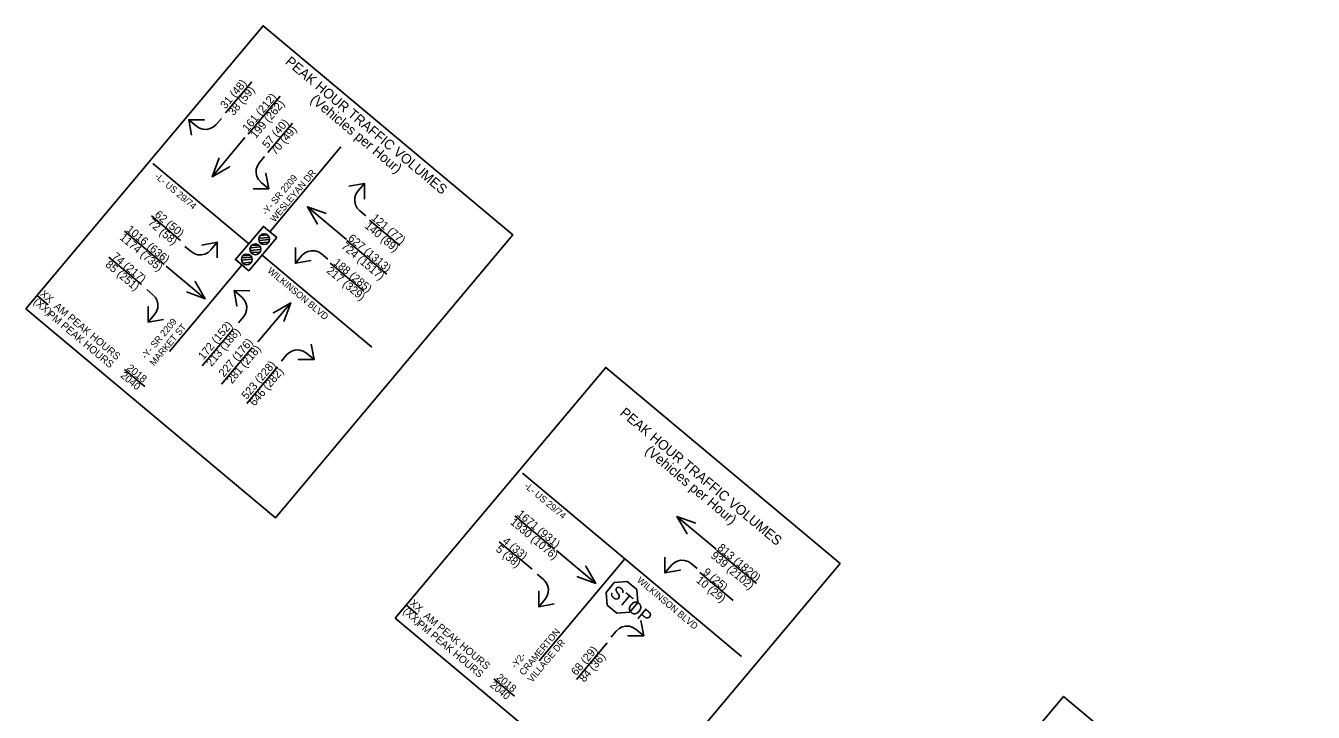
# Model space of a CAD drawing. Extents: x 1257249 to 1258387, y 800228 to 800957.
# Drawn here: x 1257736 to 1258387, y 800608 to 800956 of the extents above; entities that cross this region are included whole.
import ezdxf

# ---------------------------------------------------------------- set-up
doc = ezdxf.new("R2010")
doc.units = 0
for name, color, linetype in [('Exist PHM Traffic Signal CELL', 7, 'Continuous'), ('Pattern 1', 7, 'Continuous'), ('Prop DSN Text', 7, 'Continuous')]:
    doc.layers.add(name, color=color, linetype=linetype)

msp = doc.modelspace()

# ---------------------------------------------------------------- linework, layer by layer
at = {"layer": 'Exist PHM Traffic Signal CELL'}
for p, q in [((1257853.86, 800848.37), (1257859.23, 800848.84)), ((1257853.86, 800847.31), (1257859.33, 800847.7)), ((1257854.58, 800849.72), (1257858.32, 800850.1)), ((1257849.45, 800843.55), (1257854.6, 800843.96)), ((1257849.47, 800842.22), (1257854.84, 800842.69)), ((1257850.01, 800841.11), (1257854.56, 800841.38)), ((1257850.31, 800844.78), (1257853.71, 800844.94)), ((1257854.55, 800846.08), (1257858.77, 800846.45)), ((1257845.09, 800838.39), (1257850.34, 800838.72)), ((1257845.19, 800837.25), (1257850.56, 800837.72)), ((1257845.78, 800839.52), (1257849.57, 800839.85)), ((1257845.8, 800835.84), (1257849.98, 800836.25))]:
    msp.add_line(p, q, dxfattribs=at)
msp.add_lwpolyline([(1257862.94, 800848.75), (1257856.19, 800854.41), (1257842.05, 800837.55), (1257848.81, 800831.89)], close=True, dxfattribs=at)
for centre in [(1257856.58, 800847.91), (1257852.15, 800842.77), (1257847.79, 800837.65)]:
    msp.add_circle(centre, 2.74, dxfattribs=at)
at = {"layer": 'Pattern 1'}
for points in [[(1257834.94, 800909.07), (1257832.34, 800905.97), (1257830.97, 800904.72), (1257829.33, 800903.86), (1257827.53, 800903.46), (1257825.68, 800903.54), (1257823.91, 800904.1), (1257822.35, 800905.09), (1257818.47, 800908.34), (1257826.34, 800908.32), (1257818.47, 800908.34), (1257819.88, 800900.54)], [(1257846.88, 800899.31), (1257830.29, 800879.52), (1257839.06, 800884.59), (1257830.29, 800879.52), (1257833.75, 800889.04)], [(1257856.75, 800889.77), (1257854.15, 800886.66), (1257853.16, 800885.1), (1257852.6, 800883.34), (1257852.52, 800881.49), (1257852.93, 800879.68), (1257853.78, 800878.04), (1257855.03, 800876.68), (1257858.91, 800873.43), (1257857.52, 800881.17), (1257858.91, 800873.43), (1257850.98, 800873.45)], [(1257908.04, 800859.67), (1257904.93, 800862.27), (1257903.68, 800863.63), (1257902.83, 800865.27), (1257902.43, 800867.08), (1257902.51, 800868.93), (1257903.06, 800870.69), (1257904.05, 800872.25), (1257907.31, 800876.13), (1257907.29, 800868.26), (1257907.31, 800876.13), (1257899.5, 800874.72)], [(1257898.27, 800847.72), (1257878.48, 800864.31), (1257883.55, 800855.54), (1257878.48, 800864.31), (1257888, 800860.85)], [(1257816.49, 800844.2), (1257819.6, 800841.6), (1257821.16, 800840.6), (1257822.92, 800840.05), (1257824.77, 800839.97), (1257826.58, 800840.37), (1257828.22, 800841.23), (1257829.58, 800842.48), (1257832.83, 800846.36), (1257825.08, 800844.96), (1257832.83, 800846.36), (1257832.81, 800838.43)], [(1257816.49, 800844.2), (1257819.6, 800841.6), (1257821.16, 800840.6), (1257822.92, 800840.05), (1257824.77, 800839.97), (1257826.58, 800840.37), (1257828.22, 800841.23), (1257829.58, 800842.48), (1257832.83, 800846.36), (1257825.08, 800844.96), (1257832.83, 800846.36), (1257832.81, 800838.43)], [(1257888.73, 800837.85), (1257885.63, 800840.45), (1257884.07, 800841.44), (1257882.3, 800842), (1257880.45, 800842.08), (1257878.65, 800841.68), (1257877, 800840.82), (1257875.64, 800839.57), (1257872.39, 800835.69), (1257880.14, 800837.09), (1257872.39, 800835.69), (1257872.41, 800843.62)], [(1257806.95, 800834.32), (1257826.74, 800817.74), (1257821.67, 800826.5), (1257826.74, 800817.74), (1257817.22, 800821.2)], [(1257806.95, 800834.32), (1257826.74, 800817.74), (1257821.67, 800826.5), (1257826.74, 800817.74), (1257817.22, 800821.2)], [(1257797.18, 800822.38), (1257800.29, 800819.78), (1257801.54, 800818.42), (1257802.39, 800816.78), (1257802.8, 800814.97), (1257802.72, 800813.12), (1257802.16, 800811.36), (1257801.17, 800809.8), (1257797.92, 800805.92), (1257797.94, 800813.79), (1257797.92, 800805.92), (1257805.72, 800807.32)], [(1257797.18, 800822.38), (1257800.29, 800819.78), (1257801.54, 800818.42), (1257802.39, 800816.78), (1257802.8, 800814.97), (1257802.72, 800813.12), (1257802.16, 800811.36), (1257801.17, 800809.8), (1257797.92, 800805.92), (1257797.94, 800813.79), (1257797.92, 800805.92), (1257805.72, 800807.32)], [(1257843.55, 800805.51), (1257846.15, 800808.62), (1257847.15, 800810.18), (1257847.7, 800811.94), (1257847.78, 800813.79), (1257847.38, 800815.6), (1257846.52, 800817.24), (1257845.27, 800818.6), (1257841.39, 800821.85), (1257842.79, 800814.11), (1257841.39, 800821.85), (1257849.32, 800821.83)], [(1257853.43, 800795.97), (1257870.01, 800815.76), (1257861.25, 800810.69), (1257870.01, 800815.76), (1257866.55, 800806.24)], [(1257865.37, 800786.2), (1257867.97, 800789.31), (1257869.33, 800790.56), (1257870.97, 800791.41), (1257872.78, 800791.82), (1257874.63, 800791.74), (1257876.39, 800791.18), (1257877.95, 800790.19), (1257881.83, 800786.94), (1257873.96, 800786.96), (1257881.83, 800786.94), (1257880.42, 800794.74)], [(1258085.28, 800691), (1258065.49, 800707.58), (1258070.56, 800698.82), (1258065.49, 800707.58), (1258075.01, 800704.12)], [(1258004.56, 800690.25), (1258024.35, 800673.66), (1258019.28, 800682.43), (1258024.35, 800673.66), (1258014.83, 800677.12)], [(1258004.56, 800690.25), (1258024.35, 800673.66), (1258019.28, 800682.43), (1258024.35, 800673.66), (1258014.83, 800677.12)], [(1258075.74, 800681.12), (1258072.63, 800683.72), (1258071.07, 800684.72), (1258069.31, 800685.27), (1258067.46, 800685.35), (1258065.65, 800684.95), (1258064.01, 800684.09), (1258062.65, 800682.84), (1258059.4, 800678.96), (1258067.14, 800680.36), (1258059.4, 800678.96), (1258059.42, 800686.89)], [(1257994.79, 800678.3), (1257997.9, 800675.7), (1257999.15, 800674.34), (1258000, 800672.7), (1258000.41, 800670.89), (1258000.33, 800669.04), (1257999.77, 800667.28), (1257998.78, 800665.72), (1257995.53, 800661.84), (1257995.55, 800669.71), (1257995.53, 800661.84), (1258003.33, 800663.25)], [(1257994.79, 800678.3), (1257997.9, 800675.7), (1257999.15, 800674.34), (1258000, 800672.7), (1258000.41, 800670.89), (1258000.33, 800669.04), (1257999.77, 800667.28), (1257998.78, 800665.72), (1257995.53, 800661.84), (1257995.55, 800669.71), (1257995.53, 800661.84), (1258003.33, 800663.25)], [(1258032.18, 800646.4), (1258034.78, 800649.51), (1258036.15, 800650.76), (1258037.79, 800651.61), (1258039.59, 800652.01), (1258041.44, 800651.93), (1258043.21, 800651.38), (1258044.77, 800650.39), (1258048.65, 800647.13), (1258040.78, 800647.15), (1258048.65, 800647.13), (1258047.24, 800654.94)]]:
    msp.add_lwpolyline(points, dxfattribs=at)
at = {"layer": 'Prop DSN Text'}
for p, q in [((1257850.31, 800927.64), (1257837.1, 800911.88)), ((1257864.76, 800920.39), (1257848.53, 800901.02)), ((1257870.86, 800906.57), (1257858.49, 800891.81)), ((1257895.37, 800894.58), (1257859.44, 800851.71)), ((1257800.28, 800886.21), (1257848.63, 800845.69)), ((1257799.56, 800859.7), (1257814.33, 800847.32)), ((1257909.83, 800857.58), (1257925.26, 800844.64)), ((1257785.87, 800851.94), (1257805.97, 800835.09)), ((1257898.46, 800847.18), (1257918.68, 800830.24)), ((1257777.93, 800838.84), (1257794.53, 800824.92)), ((1257845.14, 800834.65), (1257808.66, 800791.11)), ((1257855.64, 800839.81), (1257911.11, 800793.32)), ((1257890.04, 800835.83), (1257906.96, 800821.65)), ((1257741.82, 800819.24), (1257747.25, 800814.69)), ((1257840.8, 800802.24), (1257825.29, 800783.74)), ((1257850.57, 800793.02), (1257835.06, 800774.51)), ((1257863.38, 800783.29), (1257847.87, 800764.78)), ((1257785.86, 800782), (1257796.29, 800773.26)), ((1257987.29, 800729.48), (1258039.02, 800686.12)), ((1257983.48, 800707.86), (1258003.58, 800691.02)), ((1257975.54, 800694.76), (1257992.14, 800680.84)), ((1258039.02, 800686.12), (1257995.67, 800634.39)), ((1258039.02, 800686.12), (1258098.12, 800636.59)), ((1258085.47, 800690.46), (1258105.68, 800673.52)), ((1258077.05, 800679.1), (1258093.97, 800664.92)), ((1258029.63, 800669.12), (1258033.76, 800674.05)), ((1258033.76, 800674.05), (1258040.21, 800674.63)), ((1258040.21, 800674.63), (1258045.16, 800670.49)), ((1258030.16, 800662.67), (1258029.63, 800669.12)), ((1258045.16, 800670.49), (1258045.71, 800664.03)), ((1257928.83, 800662.51), (1257934.26, 800657.96)), ((1258035.12, 800658.52), (1258030.16, 800662.67)), ((1258041.57, 800659.09), (1258035.12, 800658.52)), ((1258045.71, 800664.03), (1258041.57, 800659.09)), ((1258030.19, 800643.49), (1258014.68, 800624.98)), ((1257972.87, 800625.27), (1257983.29, 800616.53))]:
    msp.add_line(p, q, dxfattribs=at)
for points in [[(1257735.95, 800812.7), (1257862.29, 800706.82), (1257982.36, 800850.08), (1257856.02, 800955.96)], [(1257922.96, 800655.97), (1258041.53, 800556.6), (1258148, 800683.65), (1258029.43, 800783.02)], [(1258141.05, 800473.19), (1258267.38, 800367.31), (1258387.45, 800510.58), (1258261.11, 800616.46)]]:
    msp.add_lwpolyline(points, close=True, dxfattribs=at)

# ---------------------------------------------------------------- texts
for s, height, rotation, p in [('PEAK HOUR TRAFFIC VOLUMES', 5, 320.03429, (1257866.87, 800937.06)), ('31 (48)', 4.05, 50.03429, (1257837.04, 800913.57)), ('38 (59)', 4.05, 50.03429, (1257841.11, 800910.16)), ('161 (212)', 4.05, 50.03429, (1257848.27, 800901.97)), ('(Vehicles per Hour)', 5, 320.03429, (1257879.55, 800917.88)), ('199 (262)', 4.05, 50.03429, (1257852.34, 800898.56)), ('57 (40)', 4.05, 50.03429, (1257858.28, 800893.59)), ('70 (49)', 4.05, 50.03429, (1257862.35, 800890.18)), ('-L- US 29/74 ', 3.375, 320.03429, (1257800.97, 800879.17)), ('-Y- SR 2209', 3.375, 50.03429, (1257857.69, 800859.79)), ('WESLEYAN DR', 3.375, 50.03429, (1257861.89, 800856.27)), ('62 (50)', 4.05, 320.03429, (1257800.85, 800859.75)), ('1016 (636)', 4.05, 320.03429, (1257786.57, 800852.24)), ('72 (58)', 4.05, 320.03429, (1257797.44, 800855.68)), ('140 (89)', 4.05, 320.03429, (1257907.14, 800854.03)), ('121 (77)', 4.05, 320.03429, (1257910.55, 800858.1)), ('1174 (735)', 4.05, 320.03429, (1257783.16, 800848.17)), ('627 (1313)', 4.05, 320.03429, (1257898.68, 800847.81)), ('74 (217)', 4.05, 320.03429, (1257779.29, 800838.53)), ('724 (1517)', 4.05, 320.03429, (1257895.27, 800843.74)), ('85 (251)', 4.05, 320.03429, (1257775.88, 800834.46)), ('188 (285)', 4.05, 320.03429, (1257891.27, 800835.47)), ('WILKINSON BLVD', 3.375, 320.03429, (1257857.94, 800831.42)), ('217 (329)', 4.05, 320.03429, (1257887.86, 800831.4)), ('XX', 3.75, 320.03429, (1257742.92, 800819.71)), ('(XX)', 3.75, 320.03429, (1257739.51, 800815.63)), ('AM PEAK HOURS', 3.75, 320.03429, (1257749.91, 800813.31)), ('PM PEAK HOURS', 3.75, 320.03429, (1257746.5, 800809.24)), ('-Y- SR 2209', 3.375, 50.03429, (1257796.69, 800787.01)), ('MARKET ST', 3.375, 50.03429, (1257800.9, 800783.49)), ('172 (152)', 4.05, 50.03429, (1257825.87, 800786.54)), ('213 (188)', 4.05, 50.03429, (1257829.94, 800783.13)), ('227 (176)', 4.05, 50.03429, (1257836.24, 800777.85)), ('281 (218)', 4.05, 50.03429, (1257840.31, 800774.44)), ('2018', 3.75, 320.03429, (1257786.74, 800782.16)), ('523 (228)', 4.05, 50.03429, (1257847.76, 800766.51)), ('646 (282)', 4.05, 50.03429, (1257851.83, 800763.1)), ('2040', 3.75, 320.03429, (1257783.58, 800778.39)), ('PEAK HOUR TRAFFIC VOLUMES', 5, 320.03429, (1258036.23, 800759.28)), ('(Vehicles per Hour)', 5, 320.03429, (1258048.91, 800740.1)), ('-L- US 29/74 ', 3.375, 320.03429, (1257987.97, 800722.44)), ('1930 (1076)', 4.05, 320.03429, (1257980.77, 800704.09)), ('1671 (931)', 4.05, 320.03429, (1257984.18, 800708.16)), ('5 (38)', 4.05, 320.03429, (1257973.49, 800690.38)), ('4 (33)', 4.05, 320.03429, (1257976.9, 800694.45)), ('813 (1820)', 4.05, 320.03429, (1258085.69, 800691.08)), ('939 (2102)', 4.05, 320.03429, (1258082.28, 800687.02)), ('9 (25)', 4.05, 320.03429, (1258078.28, 800678.75)), ('STOP', 6.593, 320.03429, (1258030.93, 800668.12)), ('WILKINSON BLVD', 3.375, 320.03429, (1258044.95, 800674.69)), ('10 (29)', 4.05, 320.03429, (1258074.87, 800674.68)), ('XX', 3.75, 320.03429, (1257929.93, 800662.98)), ('(XX)', 3.75, 320.03429, (1257926.51, 800658.91)), ('PM PEAK HOURS', 3.75, 320.03429, (1257933.51, 800652.51)), ('AM PEAK HOURS', 3.75, 320.03429, (1257936.92, 800656.58)), ('CRAMERTON', 3.375, 50.03429, (1257987.9, 800626.76)), ('VILLAGE DR', 3.375, 50.03429, (1257992.11, 800623.24)), ('68 (29)', 4.05, 50.03429, (1258014.57, 800626.71)), ('-Y2-', 3.375, 50.03429, (1257983.7, 800630.29)), ('84 (36)', 4.05, 50.03429, (1258018.64, 800623.3)), ('2018', 3.75, 320.03429, (1257973.75, 800625.43)), ('2040', 3.75, 320.03429, (1257970.59, 800621.66))]:
    msp.add_text(s, height=height, rotation=rotation, dxfattribs=at).set_placement(p)

doc.saveas('drawing.dxf')
